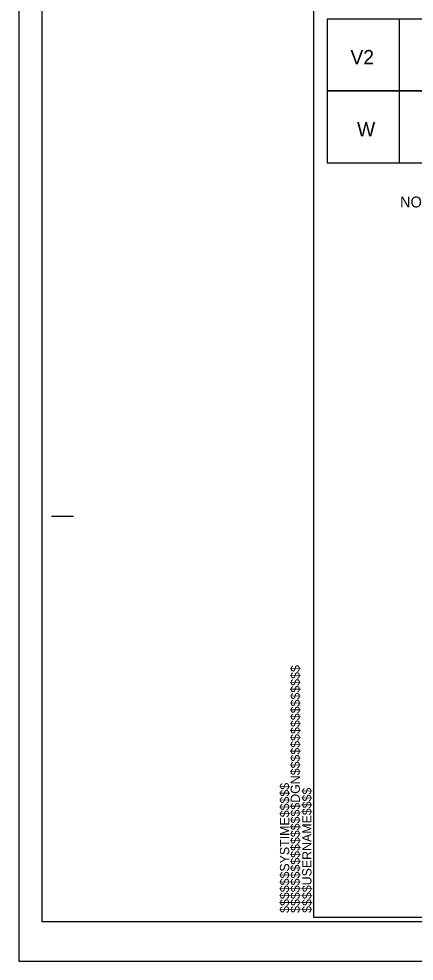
# Model space of a CAD drawing. Extents: x 1497225 to 1499181, y 579958 to 582278.
# Drawn here: x 1497225 to 1497449, y 581178 to 581713 of the extents above; entities that cross this region are included whole.
import ezdxf

# ---------------------------------------------------------------- set-up
doc = ezdxf.new("R2010")
doc.units = 0
for name, color, linetype in [('Old_Level_4', 7, 'Continuous'), ('Prop Pavement Schedule Description CELL', 7, 'Continuous'), ('Sheet Cutting Line CELL', 7, 'Continuous'), ('Sheet Plot Border Inside CELL', 7, 'Continuous'), ('Sheet Plot Border Outside CELL', 7, 'Continuous'), ('Sheet Typical CELL', 7, 'Continuous')]:
    doc.layers.add(name, color=color, linetype=linetype)

msp = doc.modelspace()

# ---------------------------------------------------------------- linework, layer by layer
at = {"layer": 'Prop Pavement Schedule Description CELL'}
for points in [[(1497441.11, 581671.59), (1497400.21, 581671.59), (1497400.21, 581712.5), (1497800.21, 581712.5), (1497800.21, 581671.59), (1497441.11, 581671.59), (1497441.11, 581712.5)], [(1497441.11, 581630.68), (1497400.21, 581630.68), (1497400.21, 581671.59), (1497800.21, 581671.59), (1497800.21, 581630.68), (1497441.11, 581630.68), (1497441.11, 581671.59)]]:
    msp.add_lwpolyline(points, dxfattribs=at)
at = {"layer": 'Sheet Cutting Line CELL'}
for p, q in [((1497225.23, 582277.96), (1497225.23, 581177.96)), ((1497225.23, 581177.96), (1498909.23, 581177.96))]:
    msp.add_line(p, q, dxfattribs=at)
at = {"layer": 'Sheet Plot Border Inside CELL'}
msp.add_lwpolyline([(1498904.73, 582255.51), (1497238.23, 582255.51), (1497238.23, 581200.41), (1498904.73, 581200.41)], close=True, dxfattribs=at)
at = {"layer": 'Sheet Plot Border Outside CELL'}
msp.add_lwpolyline([(1498909.23, 582277.96), (1497225.23, 582277.96), (1497225.23, 581177.96), (1498909.23, 581177.96)], close=True, dxfattribs=at)
at = {"layer": 'Sheet Typical CELL'}
for p, q in [((1497243.73, 581430.46), (1497256.23, 581430.46)), ((1497392.23, 581202.96), (1497392.23, 581202.96)), ((1497392.23, 581202.96), (1497392.23, 581202.96)), ((1497392.23, 581202.96), (1497392.23, 581202.96)), ((1497392.23, 581202.96), (1497392.23, 581202.96)), ((1497392.23, 581202.96), (1497392.23, 581202.96)), ((1497392.23, 581202.96), (1497392.23, 581202.96))]:
    msp.add_line(p, q, dxfattribs=at)
msp.add_lwpolyline([(1498892.23, 582252.96), (1497392.23, 582252.96), (1497392.23, 581202.96), (1498892.23, 581202.96)], close=True, dxfattribs=at)
msp.add_lwpolyline([(1497429.73, 581202.96), (1497429.73, 581202.96)], dxfattribs=at)

# ---------------------------------------------------------------- texts
at = {"layer": 'Old_Level_4'}
msp.add_text('NOTE: PAVEMENT EDGE SLOPES ARE 1:1 UNLESS SHOWN OTHERWISE', height=6.1875, rotation=360, dxfattribs=at).set_placement((1497441.36, 581605.52))
at = {"layer": 'Prop Pavement Schedule Description CELL'}
for s, height, p in [('V2', 8.167, (1497413.27, 581686.67)), ('W', 8.17, (1497417.01, 581645.77))]:
    msp.add_text(s, height=height, dxfattribs=at).set_placement(p)
at = {"layer": 'Sheet Typical CELL'}
for s, p in [('$$$$$$$$$$$$$$$$DGN$$$$$$$$$$$$$$$$', (1497384.58, 581205.32)), ('$$$$$$SYSTIME$$$$$', (1497378.53, 581205.32)), ('$$$$USERNAME$$$$', (1497391.15, 581205.33))]:
    msp.add_text(s, height=5.25, rotation=90, dxfattribs=at).set_placement(p)

doc.saveas('drawing.dxf')
